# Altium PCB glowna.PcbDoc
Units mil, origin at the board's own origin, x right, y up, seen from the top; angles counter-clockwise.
Board outline 3802 x 3105 mil, 2 copper layers (Top Layer, Bottom Layer); 129 components, 124 nets, 433 pads, 98 vias.
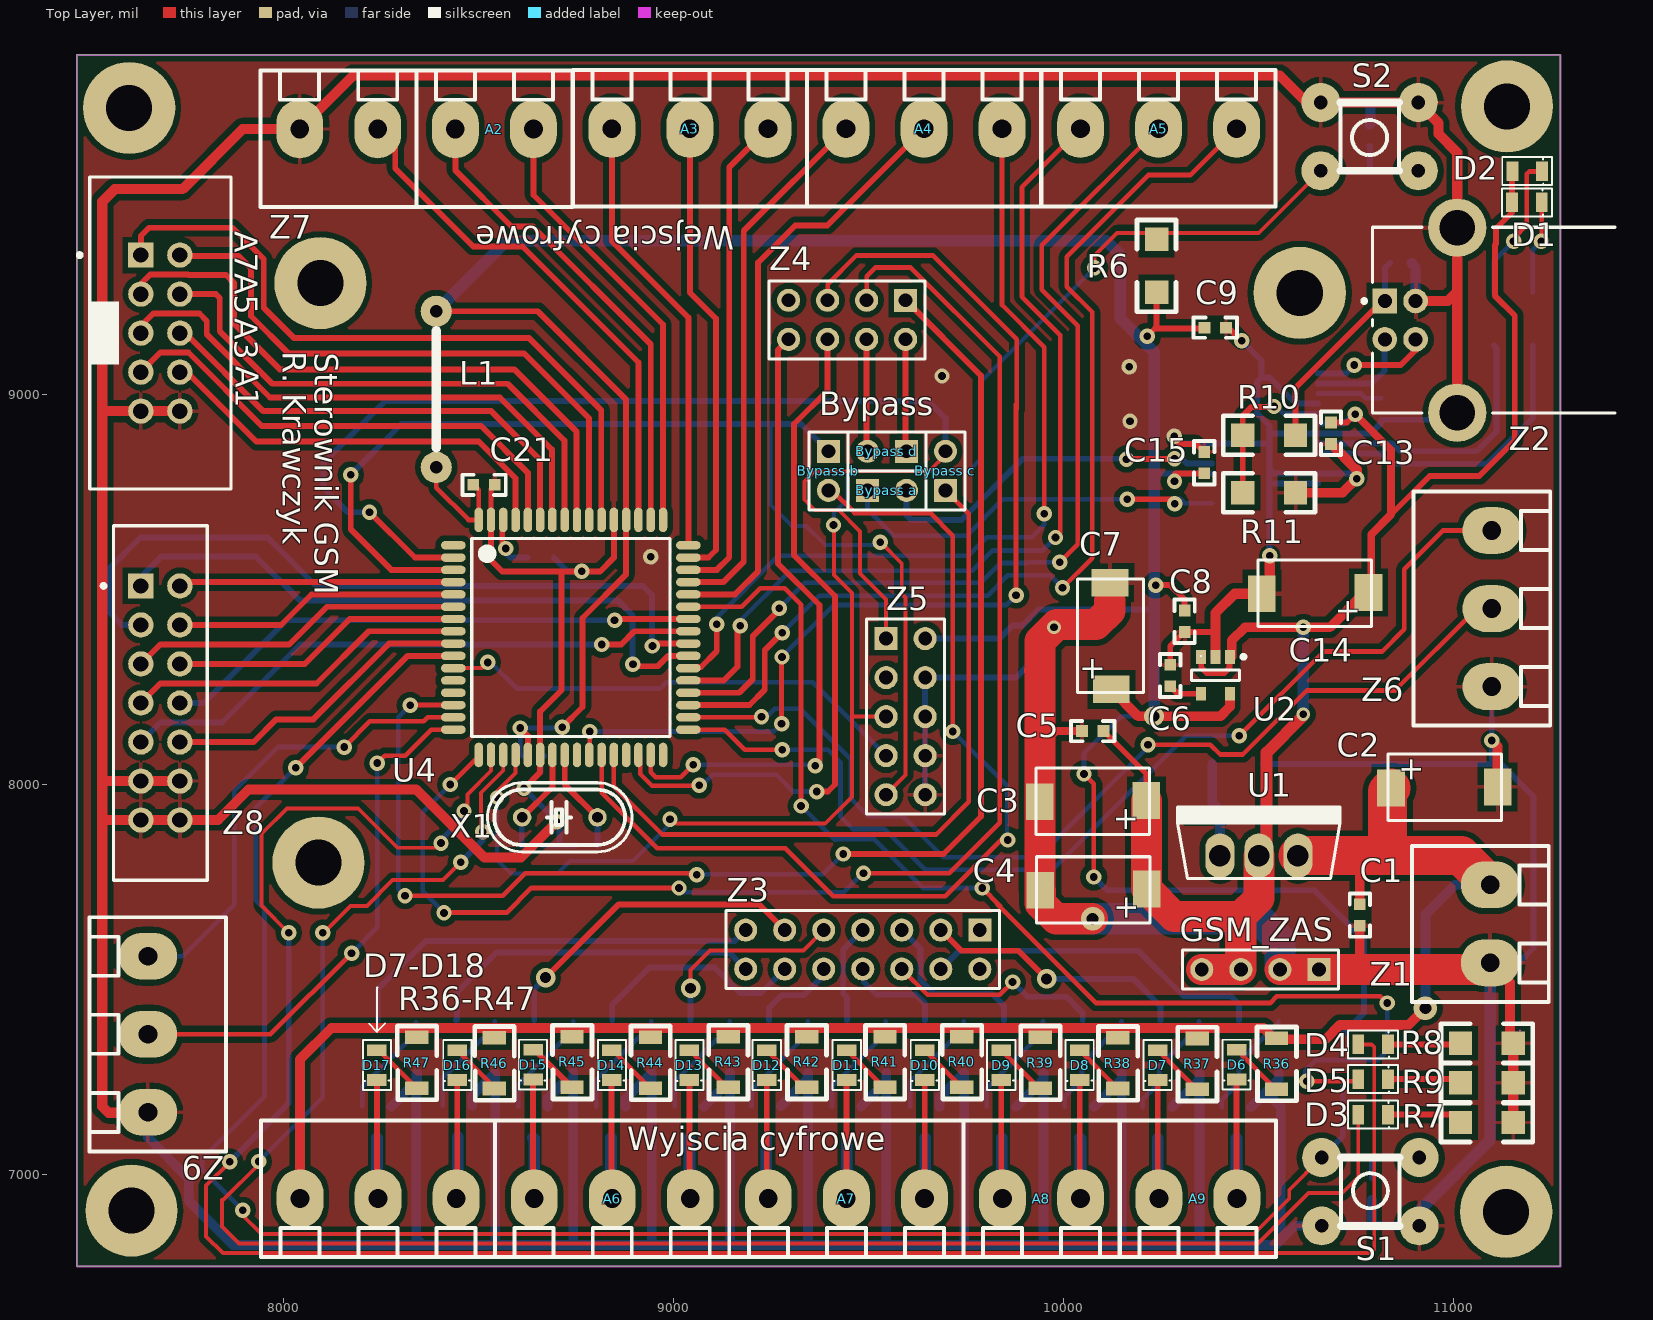
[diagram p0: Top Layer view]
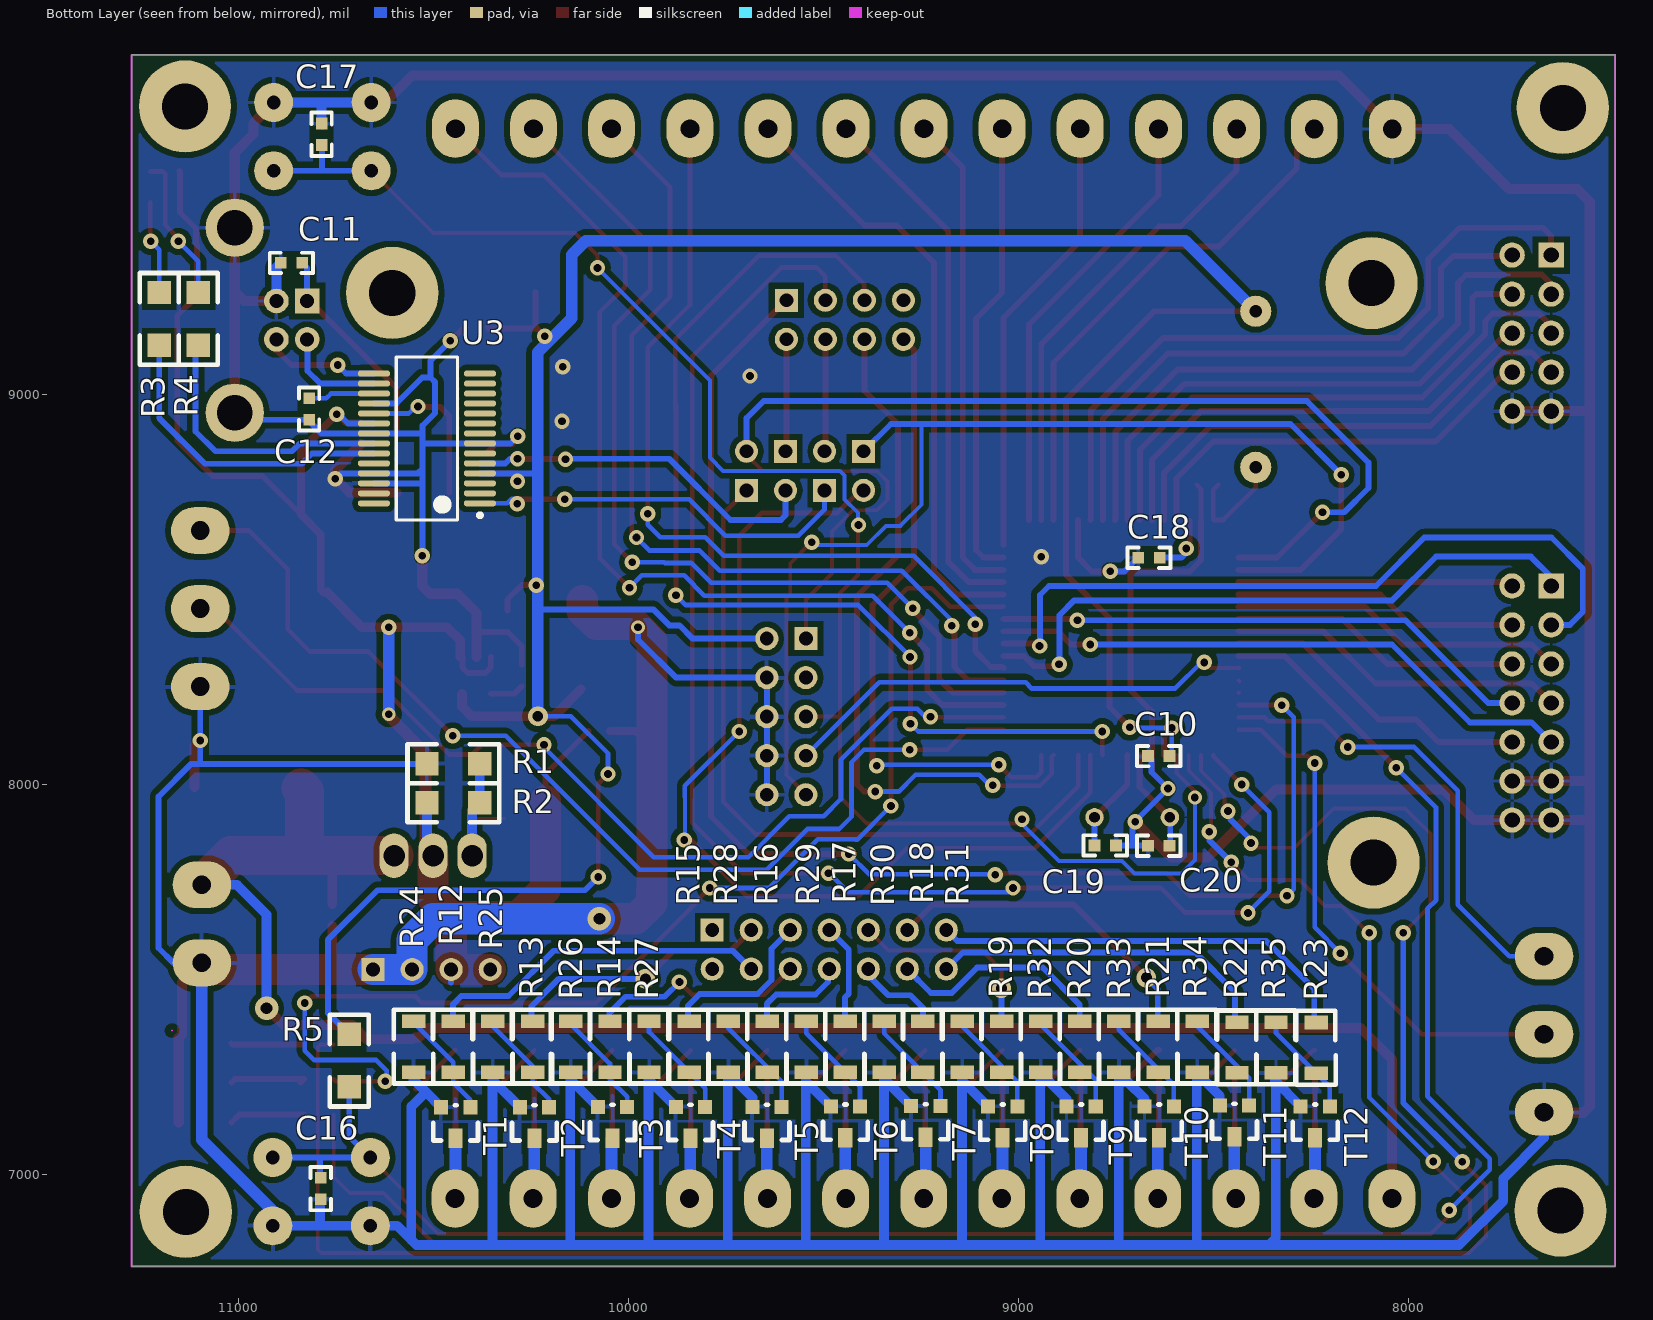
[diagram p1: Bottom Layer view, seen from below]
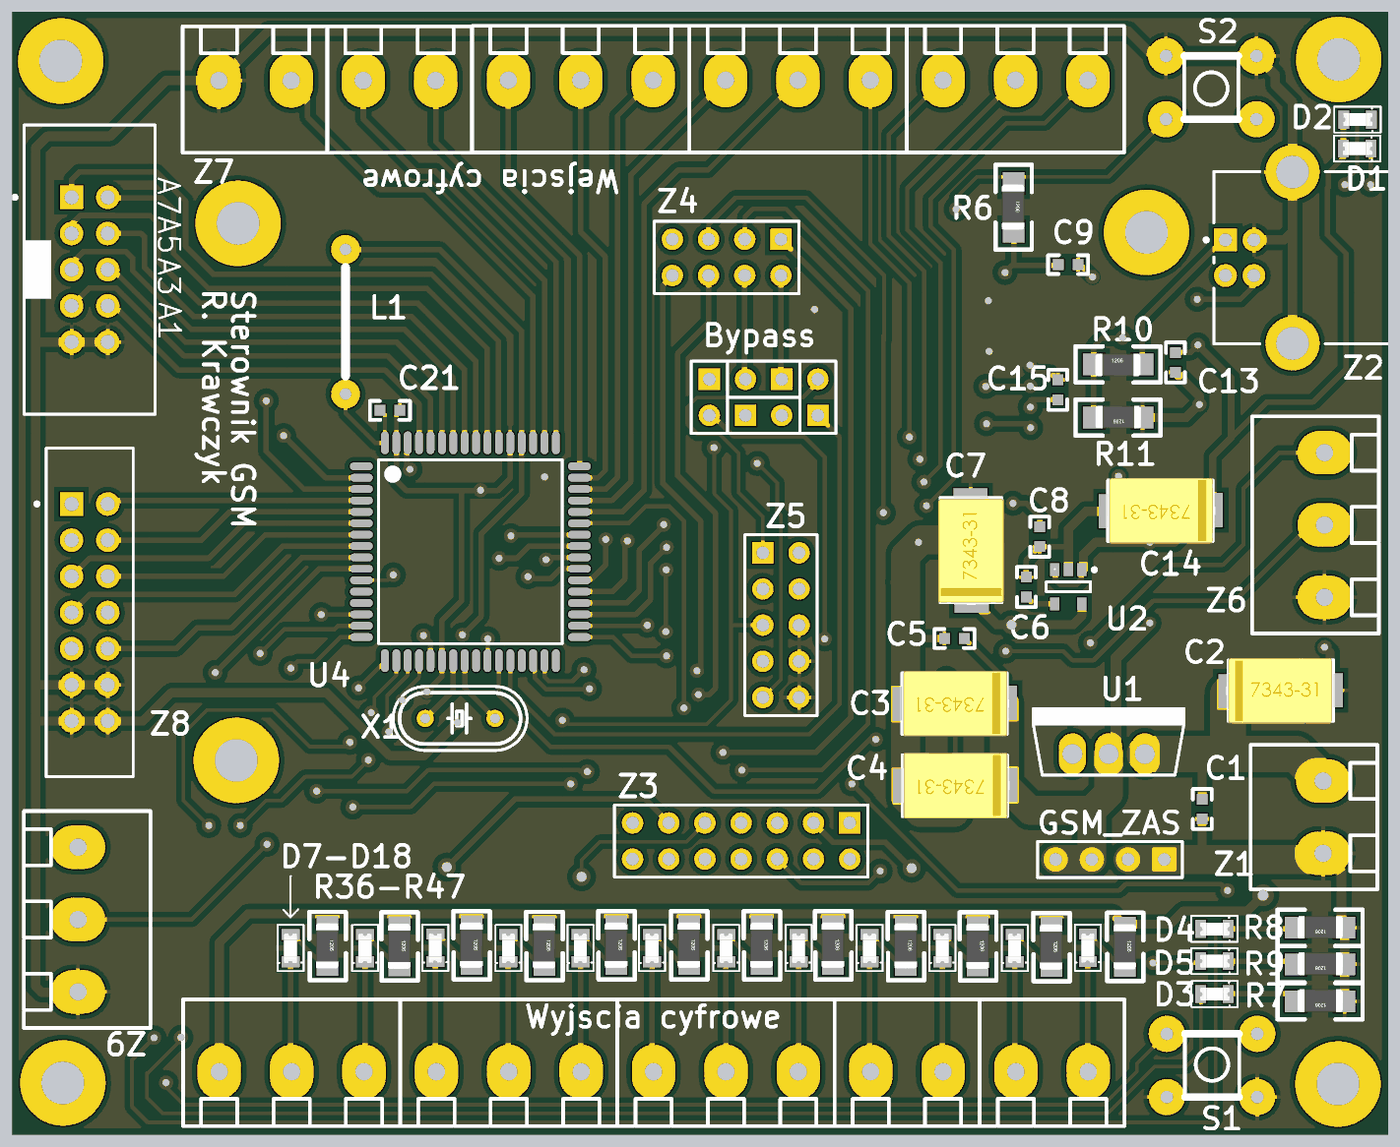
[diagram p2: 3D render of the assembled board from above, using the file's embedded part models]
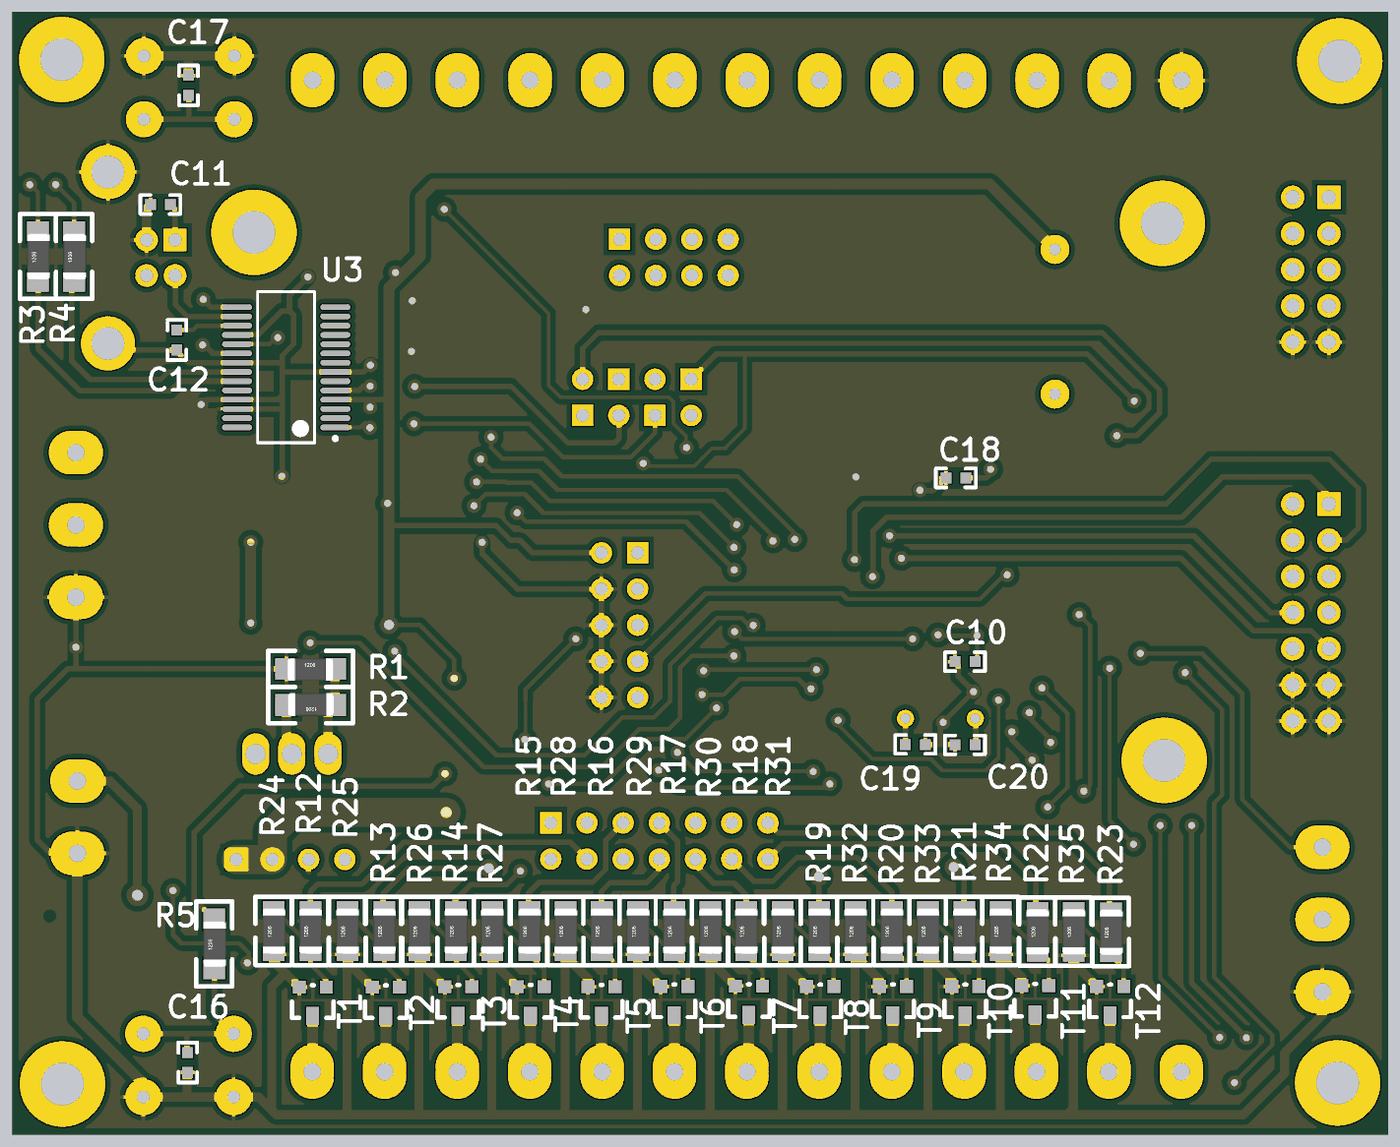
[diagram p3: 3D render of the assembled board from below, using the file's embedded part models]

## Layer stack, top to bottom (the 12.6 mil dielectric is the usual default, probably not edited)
Top Layer: signal copper 1.4
Dielectric: dielectric 12.6, FR-4, Dk 4.8
Bottom Layer: signal copper 1.4

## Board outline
11273,9870 7471,9870 7471,6765 11273,6765

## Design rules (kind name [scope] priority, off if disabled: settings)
Clearance [All] p1: gap=15
PlaneConnect PlaneConnect_1 [All] p1: planeconnectstyle=Relief reliefexpansion=20 reliefentries=4 reliefconductorwidth=10 reliefairgap=10
PolygonConnect [(InNet('GND') AND IsVia)] p1: connectstyle=Direct reliefconductorwidth=10 reliefentries=4 polygonreliefangle="90 Angle"
PolygonConnect PolygonConnect_1 [All] p2: connectstyle=Relief reliefconductorwidth=10 reliefentries=4 polygonreliefangle="90 Angle"
RoutingVias [All] p1: holewidth=19.68 width=39.37 viastyle="Through Hole" minholewidth=19.68 minwidth=31.5 maxholewidth=19.68 maxwidth=39.37
SilkscreenOverComponentPads [All] p1: minsilkscreentomaskgap=10
SolderMaskExpansion [All] p1: expansion=4
Width [All] p1: maxlimit=100 minlimit=10 preferedwidth=30 toplayer_prefwidth=10 minimp=50.000000 maximp=50.000000 favimp=50.000000
26 further rules are at their usual default settings.

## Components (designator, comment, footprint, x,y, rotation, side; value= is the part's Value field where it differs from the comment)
A2 "ARK2_1" ARK2 9131,9650 r0 top
A3 "ARK3" ARK3 8842,9681 r0 top
A4 "ARK3" ARK3 9442,9681 r0 top
A5 "ARK3" ARK3 10043,9681 r0 top
A6 "ARK3" ARK3 9043,6939 r180 top
A7 "ARK3" ARK3 9643,6939 r180 top
A8 "ARK2_1" ARK2 9353,6969 r180 top
A9 "ARK2_1" ARK2 9754,6969 r180 top locked
"Bypass a" "Header 2" HDR1X2 9497,8754 r0 top
"Bypass b" "Header 2" HDR1X2 9397,8854 r270 top
"Bypass c" "Header 2" HDR1X2 9697,8754 r90 top
"Bypass d" "Header 2" HDR1X2 9597,8854 r180 top
C1 "100nF" 0603 10759,7693 r270 top
C2 "CAP2" smd-d 10976,7993 r270 top
C3 "1500uF" smd-d 10075,7957 r90 top
C4 "1500uF" smd-d 10076,7730 r90 top
C5 "100nF" 0603 10102,8137 r180 top
C6 "100nF" 0603 10273,8307 r270 top
C7 "1500uF" smd-d 10120,8381 r0 top
C8 "3x100nF" 0603 10310,8446 r270 top
C9 "3x100nF" 0603 10361,9171 r0 top
C10 "3x100nF" 0603 8613,8073 r0 bottom
C11 "100nF" 0603 10836,9337 r0 bottom
C12 "100nF" 0603 10818,8990 r270 bottom
C13 "100nF" 0603 10685,8928 r270 top
C14 "100uF" smd-d 10644,8490 r90 top
C15 "100nF" 0603 10360,8797.43 r90 top
C16 "33pF" 0603 10788,6937 r90 bottom
C17 "33pF" 0603 10786,9694 r270 bottom
C18 "100nF" 0603 8638,8581 r0 bottom
C19 "33pF" 0603 8805,7844 r180 bottom
C20 "33pF" 0603 8613,7843 r0 bottom
C21 "100nF" 0603 8542,8768 r180 top
D1 "" led_0805 11174,9498 r270 top
D2 "" led_0805 11175,9578 r270 top
D3 "" led_0805 10780,7160 r270 top
D4 "" led_0805 10780,7340 r270 top
D5 "" led_0805 10780,7251 r270 top
D6 "" led_0805 10449,7295 r180 top
D7 "" led_0805 10247,7294 r180 top
D8 "" led_0805 10047,7294 r180 top
D9 "" led_0805 9846,7294 r180 top
D10 "" led_0805 9650,7294 r180 top
D11 "" led_0805 9450,7294 r180 top
D12 "" led_0805 9245,7294 r180 top
D13 "" led_0805 9047,7294 r180 top
D14 "" led_0805 8848,7294 r180 top
D15 "" led_0805 8646,7295 r180 top
D16 "" led_0805 8452,7294 r180 top
D17 "" led_0805 8246,7294 r180 top
GSM_ZAS "Header 4" HDR1X4 10654,7526 r180 top locked
L1 "10uH" r4 8392,8813 r0 top
R1 "RES" 1206#1 10516,8053 r180 bottom
R2 "RES" 1206#1 10381,7953 r0 bottom
R3 "470R" 1206#1 11202,9126 r90 bottom
R4 "470R" 1206#1 11102,9126 r90 bottom
R5 "10k" 1206#1 10715,7225 r90 bottom
R6 "10k" 1206#1 10238,9397 r270 top
R7 "1k" 1206#1 11152,7134 r180 top
R8 "1k" 1206#1 11152,7337 r180 top
R9 "1k" 1206#1 11152,7236 r180 top
R10 "4,7k" 1206#1 10459,8895 r0 top
R11 "10k" 1206#1 10594,8748 r180 top
R12 "2,2k" 1206#2 10450,7261 r90 bottom
R13 "2,2k" 1206#2 10246,7261 r90 bottom
R14 "2,2k" 1206#2 10048,7261 r90 bottom
R15 "2,2k" 1206#2 9845,7261 r90 bottom
R16 "2,2k" 1206#2 9645,7261 r90 bottom
R17 "2,2k" 1206#2 9445,7261 r90 bottom
R18 "2,2k" 1206#2 9246,7261 r90 bottom
R19 "2,2k" 1206#2 9044,7261 r90 bottom
R20 "2,2k" 1206#2 8844,7261 r90 bottom
R21 "2,2k" 1206#2 8643,7261 r90 bottom
R22 "2,2k" 1206#2 8441,7259 r90 bottom
R23 "2,2k" 1206#2 8238,7258 r90 bottom
R24 "47K" 1206#2 10551,7261 r90 bottom
R25 "47K" 1206#2 10348,7261 r90 bottom
R26 "47K" 1206#2 10149,7261 r90 bottom
R27 "47K" 1206#2 9948,7261 r90 bottom
R28 "47K" 1206#2 9745,7261 r90 bottom
R29 "47K" 1206#2 9545,7261 r90 bottom
R30 "47K" 1206#2 9345,7261 r90 bottom
R31 "47K" 1206#2 9145,7261 r90 bottom
R32 "47K" 1206#2 8944,7261 r90 bottom
R33 "47K" 1206#2 8744,7261 r90 bottom
R34 "47K" 1206#2 8543,7261 r90 bottom
R35 "47K" 1206#2 8341,7259 r90 bottom
R36 "2.2k" 1206#2 10546.5,7351.5 r270 top
R37 "2.2k" 1206#2 10343,7351 r270 top
R38 "2.2k" 1206#2 10140,7353 r270 top
R39 "2.2k" 1206#2 9941,7354 r270 top
R40 "2.2k" 1206#2 9740,7356 r270 top
R41 "2.2k" 1206#2 9543,7356 r270 top
R42 "2.2k" 1206#2 9342,7356 r270 top
R43 "2.2k" 1206#2 9141,7356 r270 top
R44 "2.2k" 1206#2 8942,7354 r270 top
R45 "2.2k" 1206#2 8741,7356 r270 top
R46 "2.2k" 1206#2 8542,7353 r270 top
R47 "2.2k" 1206#2 8343,7354 r270 top
S1 "MSWITCH" MSWITCH 10661,6869 r90 top
S2 "MSWITCH" MSWITCH 10909,9748 r270 top
T1 "BC548B" "sot-23 rk" 10405,7173 r0 bottom
T2 "BC548B" "sot-23 rk" 10203,7173 r0 bottom
T3 "BC548B" "sot-23 rk" 10003,7174 r0 bottom
T4 "BC548B" "sot-23 rk" 9803,7174 r0 bottom
T5 "BC548B" "sot-23 rk" 9607,7174 r0 bottom
T6 "BC548B" "sot-23 rk" 9406,7175 r0 bottom
T7 "BC548B" "sot-23 rk" 9200,7176 r0 bottom
T8 "BC548B" "sot-23 rk" 9003,7175 r0 bottom
T9 "BC548B" "sot-23 rk" 8802,7175 r0 bottom
T10 "BC548B" "sot-23 rk" 8602,7175 r0 bottom
T11 "BC548B" "sot-23 rk" 8409,7177 r0 bottom
T12 "BC548B" "sot-23 rk" 8202,7175 r0 bottom
U1 "LM350" to220v 10500,7822 r0 top
U2 "LP3985" sot23-5al 10389,8280 r270 top
U3 "FT232RL" SSOP-28 10516,8887 r0 bottom
U4 "ATMEGA128_TQFP64" atmega128 8737,8377 r0 top locked
"Wejscia cyfrowe" "ARK2_1" ARK2 8732,9650 r0 top
"Wyjscia cyfrowe" "ARK3" ARK3 8443,6939 r180 top
X1 "X" X 8805,7916 r180 top
Z1 "12V" ARK2 11063,7053 r270 top
Z2 "USB_con" usb2.5-2h4f 11414,9190 r0 top
Z3 "GSM_GPIO" HDR2X7_CEN 9785,7627 r180 top locked
Z4 "GSM" HDR2X4_CEN 9595,9241 r180 top locked
Z5 "AVR_PROG" hdr2x5 9545,8374 r270 top
Z6 "ARK3" ARK3 11097,8651 r270 top
Z7 "Analog IN" idc2.54-v10d 7685,9157 r270 top
Z8 "Header 7X2" idc2.54-v14c 7685,8209 r270 top
Z9 "Header 3" ark3 7653,7160 r90 top

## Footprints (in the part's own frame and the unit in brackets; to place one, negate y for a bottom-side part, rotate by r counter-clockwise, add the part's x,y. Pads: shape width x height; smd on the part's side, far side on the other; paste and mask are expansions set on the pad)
0603 [mil]
  rect 30x30 smd: 1(0,0) 2(55,0)
  silkscreen extent -28,-26 83,26
1206#1 [mil]
  rect 60x60 smd: 1(0,0) 2(135,0)
  silkscreen extent -50,-50 185,50, body extent 4,-33 130,30, height 39
1206#2 [mil]
  rect 35x60 smd: 1(2,-1) 2(132,-1)
  silkscreen extent -27,-51 162,50, body extent 4,-33 130,30, height 39
ARK2 [mil]
  oval 120x150 hole 48: 1(-690,30) 2(-490,30)
  silkscreen extent -790,-170 -390,180
ARK3 [mil]
  oval 120x150 hole 48: 1(0,0) 2(200,0) 3(400,0)
  silkscreen extent -100,-200 500,150
ark3 [mil]
  oval 120x150 hole 48: 1(0,0) 2(200,0) 3(400,0)
  silkscreen extent -100,-200 500,150
atmega128 [mm] "TQFP64-0.8"
  oval 1.6x0.55 smd: 1(-7.65,6) 2(-7.65,5.2) 3(-7.65,4.4) 4(-7.65,3.6) 5(-7.65,2.8) 6(-7.65,2) 7(-7.65,1.2) 8(-7.65,0.4) 9(-7.65,-0.4) 10(-7.65,-1.2) 11(-7.65,-2) 12(-7.65,-2.8) 13(-7.65,-3.6) 14(-7.65,-4.4) 15(-7.65,-5.2) 16(-7.65,-6) 33(7.65,-6) 34(7.65,-5.2) 35(7.65,-4.4) 36(7.65,-3.6) 37(7.65,-2.8) 38(7.65,-2) 39(7.65,-1.2) 40(7.65,-0.4) 41(7.65,0.4) 42(7.65,1.2) 43(7.65,2) 44(7.65,2.8) 45(7.65,3.6) 46(7.65,4.4) 47(7.65,5.2) 48(7.65,6)
  oval 0.55x1.6 smd: 17(-6,-7.65) 18(-5.2,-7.65) 19(-4.4,-7.65) 20(-3.6,-7.65) 21(-2.8,-7.65) 22(-2,-7.65) 23(-1.2,-7.65) 24(-0.4,-7.65) 25(0.4,-7.65) 26(1.2,-7.65) 27(2,-7.65) 28(2.8,-7.65) 29(3.6,-7.65) 30(4.4,-7.65) 31(5.2,-7.65) 32(6,-7.65) 49(6,7.65) 50(5.2,7.65) 51(4.4,7.65) 52(3.6,7.65) 53(2.8,7.65) 54(2,7.65) 55(1.2,7.65) 56(0.4,7.65) 57(-0.4,7.65) 58(-1.2,7.65) 59(-2,7.65) 60(-2.8,7.65) 61(-3.6,7.65) 62(-4.4,7.65) 63(-5.2,7.65) 64(-6,7.65)
  silkscreen extent -6.45,-6.45 6.45,6.45, body extent -7,-7 7,7, height 1.2
HDR1X2 [mm] "Connector; Header; 2 Position"
  rect 1.5x1.5 hole 0.9: 1(0,0)
  round 1.5 hole 0.9: 2(2.54,0)
  silkscreen extent -1.27,-1.27 3.81,1.27
HDR1X4 [mm] "Connector; Header; 4 Position"
  rect 1.5x1.5 hole 0.9: 1(0,0)
  round 1.5 hole 0.9: 2(2.54,0) 3(5.08,0) 4(7.62,0)
  silkscreen extent -1.27,-1.27 8.89,1.27
HDR2X4_CEN [mm] "Connector; Header; 4x2 Position"
  rect 1.5x1.5 hole 0.9: 1(0,0)
  round 1.5 hole 0.9: 2(2.54,0) 3(5.08,0) 4(7.62,0) 5(0,2.54) 6(2.54,2.54) 7(5.08,2.54) 8(7.62,2.54)
  silkscreen extent -1.27,-1.27 8.89,3.81
hdr2x5 [mm] "Connector; Header; 5x2 Position"
  rect 1.5x1.5 hole 0.9: 1(0,0)
  round 1.5 hole 0.9: 2(0,2.54) 3(2.54,0) 4(2.54,2.54) 5(5.08,0) 6(5.08,2.54) 7(7.62,0) 8(7.62,2.54) 9(10.16,0) 10(10.16,2.54)
  silkscreen extent -1.27,-1.27 11.43,3.81
HDR2X7_CEN [mm] "Connector; Header; 7x2 Position"
  rect 1.5x1.5 hole 0.9: 1(0,0)
  round 1.5 hole 0.9: 2(2.54,0) 3(5.08,0) 4(7.62,0) 5(10.16,0) 6(12.7,0) 7(15.24,0) 8(0,2.54) 9(2.54,2.54) 10(5.08,2.54) 11(7.62,2.54) 12(10.16,2.54) 13(12.7,2.54) 14(15.24,2.54)
  silkscreen extent -1.27,-1.27 16.51,3.81
idc2.54-v10d [mm] "Connector; IDC, Low Profile Male Header, Thru-Hole; 10 Position; Vertical; Pitch 2.54 mm; Body 20.32 x 9.2 x 9.45 mm (LxWxH)"
  rect 1.65x1.65 hole 1: 1(-5.08,-1.27)
  round 1.65 hole 1: 2(-5.08,1.27) 3(-2.54,-1.27) 4(-2.54,1.27) 5(0,-1.27) 6(0,1.27) 7(2.54,-1.27) 8(2.54,1.27) 9(5.08,-1.27) 10(5.08,1.27)
  silkscreen extent -10.16,-5.37 10.16,4.6, body extent -10.16,-4.6 10.16,4.6, height 9.45
idc2.54-v14c [mm] "Connector; IDC, PCB Transition - 2 Rows, Thru-Hole; 14 Position; Vertical; Pitch 2.54 mm; Body 23.08 x 6.1 x 7.45 mm (LxWxH), Kinked Contacts"
  rect 1.65x1.65 hole 1: 1(-7.62,-1.27)
  round 1.65 hole 1: 2(-7.62,1.27) 3(-5.08,-1.27) 4(-5.08,1.27) 5(-2.54,-1.27) 6(-2.54,1.27) 7(0,-1.27) 8(0,1.27) 9(2.54,-1.27) 10(2.54,1.27) 11(5.08,-1.27) 12(5.08,1.27) 13(7.62,-1.27) 14(7.62,1.27)
  silkscreen extent -11.54,-3.82 11.54,3.05, body extent -11.54,-3.05 11.54,3.05, height 7.45
led_0805 [mil]
  rect 50x30 smd: 1(6,-25) 2(6,51)
  silkscreen extent -30,-51 42,77, body extent -12,-27 24,55, height 33
MSWITCH [mil]
  round 100 hole 35: 1(0,0) 1(0,-250) 2(175,0) 2(175,-250)
  silkscreen extent 0,-200 175,-50
r4 [mil]
  round 80 hole 32: 1(0,0) 2(0,400)
  silkscreen extent 0,50 0,350
smd-d [mil]
  rect 94.49x70.87 smd: 1(2,-137) 2(-1,136)
  silkscreen extent -85,-145 85,146, body extent -90,-151 91,148, height 122
sot23-5al [mm] "SOT23, 5-Leads, Body 2.9x1.6mm, Pitch 0.95mm, Lead Span 2.8mm, IPC High Density"
  rect 0.9x0.65 smd: 1(-1.2,0.95) 2(-1.2,0) 3(-1.2,-0.95) 4(1.2,-0.95) 5(1.2,0.95)
  silkscreen extent -1.32,-1.55 0.35,1.95, body extent -0.9,-1.55 0.9,1.55, height 1.45
"sot-23 rk" [mil]
  rect 35.98x35.98 smd: 1(75,0) 2(0,0)
  rect 35.98x50 smd: 3(37.99,80)
  silkscreen extent -20,-5 95,85
SSOP-28 [mm] "28-Pin SSOP 0.65 mm Pitch"
  oval 2.1x0.4 smd: 1(-3.45,4.225) 2(-3.45,3.575) 3(-3.45,2.925) 4(-3.45,2.275) 5(-3.45,1.625) 6(-3.45,0.975) 7(-3.45,0.325) 8(-3.45,-0.325) 9(-3.45,-0.975) 10(-3.45,-1.625) 11(-3.45,-2.275) 12(-3.45,-2.925) 13(-3.45,-3.575) 14(-3.45,-4.225) 15(3.45,-4.225) 16(3.45,-3.575) 17(3.45,-2.925) 18(3.45,-2.275) 19(3.45,-1.625) 20(3.45,-0.975) 21(3.45,-0.325) 22(3.45,0.325) 23(3.45,0.975) 24(3.45,1.625) 25(3.45,2.275) 26(3.45,2.925) 27(3.45,3.575) 28(3.45,4.225)
  silkscreen extent -3.57,-5.3 2,5.3, body extent -2.7,-5.3 2.7,5.3, height 2
to220v [mil]
  oval 75x114.37 hole 55: 1(-99.68,-4.25) 2(0.32,-4.25) 3(100.32,-4.25)
  Top Layer region: -185.04,86.61 -90.55,86.61 -90.55,94.49 -185.04,94.49
  silkscreen extent -208,-63 209,122
usb2.5-2h4f [mm] "Connector; USB1.1, Type B, Thru-Hole; 4 Position; Right Angle"
  rect 1.6x1.6 hole 0.92: 1(-15.01,1.25)
  round 1.6 hole 0.92: 2(-15.01,-1.25) 3(-13.01,-1.25) 4(-13.01,1.25)
  round 3.8 hole 2.3: 5(-10.3,6.02) 6(-10.3,-6.02)
  silkscreen extent -16.48,-6.05 -0.02,6.05, body extent -15.82,-6.05 -0.02,6.05, height 10.95
X [mm]
  round 1.2 hole 0.7: 1(0,0) 2(4.9,0)
  silkscreen extent -2.25,-2.25 7.15,2.25

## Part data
"Bypass a" "Bypass b" "Bypass c" "Bypass d": "Header, 2-Pin"
C1 C5 C6 C8 C9 C10 C11 C12 C13 C15 C16 C17 C18 C19 C20 C21: library part CAP, "Condenstor"
C2: "kONDENSATOR ELEKTROLITYCZNY"
C3 C4 C7 C14: library part CAP2, "kONDENSATOR ELEKTROLITYCZNY"
D1 D2 D3 D4 D5 D6 D7 D8 D9 D10 D11 D12 D13 D14 D15 D16 D17: library part LED0, "dioda elektroluminescencyjna LED"
GSM_ZAS: "Header, 4-Pin"
L1: library part cewka
R1 R2: "Rezystor"
R3 R4 R5 R6 R7 R8 R9 R10 R11 R12 R13 R14 R15 R16 R17 R18 R19 R20 R21 R22 R23 R24 R25 R26 R27 R28 R29 R30 R31 R32 R33 R34 R35 R36 R37 R38 R39 R40 R41 R42 R43 R44 R45 R46 R47: library part RES, "Rezystor"
T1 T2 T3 T4 T5 T6 T7 T8 T9 T10 T11 T12: "Tranzystor NPN"
U1: library part LM317, "3-Terminal Adjustable Positive Voltage Regulator"
U2: library part LM3985, "Stabilizator 2.8V"
U3: library part IC_FT232RL, "FT232R USB UART"
U4: "Atmel AVR 8bit - Mega Family"
X1: "Kwarc"
Z1: library part ARK
Z3: library part "Header 7X2A", "Header, 7-Pin, Dual row"
Z4: library part "Header 4X2A", "Header, 4-Pin, Dual row"
Z7: library part "Header 5X2", "Header, 5-Pin, Dual row"
Z8: "Header, 7-Pin, Dual row"
Z9: "Header, 3-Pin"

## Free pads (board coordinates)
  round 236.22 hole 118.11: 0(10605,9260) 1(8090,7800) 2(8095,9285) 3(7611,6908) 4(7605,9734) 5(11136,9738) 6(11134,6905)

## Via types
v1: diameter 39.37, hole 19.68, Top Layer to Bottom Layer, tented both sides, 89 vias
v2: diameter 35.43, hole 19.68, Top Layer to Bottom Layer, tented both sides, 3 vias
v3: diameter 50, hole 28, Top Layer to Bottom Layer, tented both sides, 3 vias
v4: diameter 60, hole 30, Top Layer to Bottom Layer, tented both sides, 2 vias
v5: diameter 51.18, hole 27.56, Top Layer to Bottom Layer, tented both sides, 1 vias

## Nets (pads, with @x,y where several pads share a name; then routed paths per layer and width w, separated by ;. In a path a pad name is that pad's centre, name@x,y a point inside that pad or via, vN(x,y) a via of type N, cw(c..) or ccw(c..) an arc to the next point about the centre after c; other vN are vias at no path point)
+2.8V: C7.1 C8.1 C9.1 C10.1 C15.1 L1.2 R5.2 R6.2 U2.5 U3.4 U4.21 U4.52 Z5.2 | length 7953.5
  Top Layer w12: v1(10052,8027) 10077,8002 v1(10077,7763)
  Top Layer w15: L1.2@8417,9213 8652,9213 8878.73,8986.27 U4.52 8878.73,8538.73 8767,8427 8767,8199 v1(8715,8147) ; v1(8607,8145) 8626.76,8125.24 U4.21 ; v1(10214,9149) 10234,9169 10238,9169 ; v1(10236,8511) 10273,8511 10310,8474 C8.1 ; R6.2 10238,9169 ; v1@10285,8785 10285,8796 10286.43,8797.43 C15.1 ; C9.1 10359,9169 10238,9169
  Top Layer w25: C7.1 10191,8175 v5(10232,8175) 10401.8,8175 10426.4,8199.6 U2.5
  Bottom Layer w12: C10.1 8607,8079 v1(8607,8145) 8713,8145 v1(8715,8147) ; v1(10052,8027) 10052,8080 10147,8175 v5(10232,8175)
  Bottom Layer w15: Z5.2 9835,8374 9869,8408 9895,8408 9936,8449 10229,8449 10232,8452 ; v1(10077,7763) 10111,7729 10643,7729 10770,7602 10770,7415 R5.2 ; 10232,8797 10232.43,8797.43 U3.4
  Bottom Layer w30: L1.2 8573,9394 10109,9394 10145,9358 10145,9195 10232,9108 10232,8797 10232,8452 v5(10232,8175)
  other v1: 10284,8777
+12V: "Wyjscia cyfrowe.3" C1.1 C2.1 R36.1 R37.1 R38.1 R39.1 R40.1 R41.1 R42.1 R43.1 R44.1 R45.1 R46.1 R47.1 U1.3 Z1.1 | length 4582.6
  Top Layer w25: 8043,6939 8043,7296 8123,7376 9342,7376 9941,7376 10512,7376 10536.5,7351.5 10546.5,7351.5 10551,7347 10671,7347 10707.5,7383.5 10883.5,7383.5 v4(10927,7427) ; 10758,7817.75 10759,7816.75 C1.1
  Top Layer w100: U1.3 10758,7817.75 10830,7817.75 ; C2.1 10830,7982 10830,7817.75 ; Z1.1 11018.25,7817.75 10830,7817.75
  Bottom Layer w25: v4(10927,7427) 10927,7667 11003,7743 Z1.1
ADC0: U4.61 Z7.8 | length 1079.6
  Top Layer w15: Z7.8 7753,9057 7931,8879 8501,8879 8595,8785 8595,8761 8595.27,8760.73 U4.61
ADC1: U4.60 Z7.7 | length 1261
  Top Layer w15: Z7.7 7685.02,9106.98 7757.02,9106.98 7945,8919 8507,8919 8626.76,8799.24 U4.60
ADC2: U4.59 Z7.6 | length 1226.5
  Top Layer w15: Z7.6 7749,9157 7949,8957 8105,8957 ; 8120,8957 8105,8957 ; U4.59 8658.26,8831.74 8533,8957 8105,8957
ADC3: U4.58 Z7.5 | length 1429.9
  Top Layer w15: Z7.5 7635,9175 7667,9207 7785,9207 7804,9188 7804,9154 7966,8992 8555,8992 8688.76,8858.24 8688.76,8679.18 U4.58
ADC4: U4.57 Z7.4 | length 1394.5
  Top Layer w15: Z7.4 7827,9257 7837,9247 7837,9162 7972,9027 8575,9027 8720.25,8881.75 8720.25,8679.18 U4.57
ADC5: U4.56 Z7.3 | length 1615.7
  Top Layer w15: Z7.3 7635,9283 7658.98,9306.98 7755.7,9306.98 7756.68,9306 7853,9306 7874,9285 7874,9181 7991,9064 8592,9064 8751.75,8904.25 8751.75,8778 ; 8751.75,8769.18 8751.75,8778 ; U4.56 8751.75,8679.18 8751.75,8778
ADC6: U4.55 Z7.2 | length 1553.9
  Top Layer w15: Z7.2 7737,9355 7885,9355 7917,9323 7917,9201 8013,9105 8617,9105 8783.24,8938.76 8783.24,8679.18 U4.55
ADC7: U4.54 Z7.1 | length 1785.9
  Top Layer w15: Z7.1 7635,9406 7656,9427 7870,9427 7950,9347 7950,9222 8028,9144 8630,9144 8814.74,8959.26 8814.74,8679.18 U4.54
ALERT1: U4.33 Z6.1 | length 2739
  Top Layer w12: U4.33 9131.22,8140.78 9183,8089 v1(9279,8089) ; v1(10450,8125) 10666,8341 10816,8341 10873,8398 10873,8552 10972,8651 Z6.1
  Bottom Layer w12: v1(9279,8089) 9396,8089 9428,8057 9428,7918 9460,7886 9541,7886 9645,7782 9971,7782 10314,8125 v1(10450,8125)
ALERT2: U4.34 Z6.2 | length 2573.1
  Top Layer w12: U4.34 v1@9224.22,8172.28 ; v1(10216,8102) 10376,8102 10401,8077 10459,8077 10623,8241 10849,8241 11059,8451 Z6.2
  Bottom Layer w12: v1@9227.68,8173.69 v1(9225.63,8173.69) 9238.68,8173.69 9259,8194 9324.94,8194 9455,8063.94 9455,7963 9499,7919 9587,7919 9692,7814 9935,7814 10216,8095 v1(10216,8102)
DIG1: A5.3 U4.35 | length 2647.1
  Top Layer w12: v1(9997,8504) 10073,8580 10073,9211 10008,9276 10008,9353 10217,9562 10324,9562 A5.3
  Top Layer w15: U4.35 9194.77,8203.77 9234,8243 9234,8344 v1(9279,8389)
  Bottom Layer w12: v1(9279,8389) 9374,8484 9805,8484 9857,8536 9965,8536 v1(9997,8504)
DIG2: A5.2 U4.36 | length 2449.3
  Top Layer w12: v1(9990,8570) 10036,8616 10036,9176 9944,9268 9944,9382 A5.2
  Top Layer w15: U4.36 9168.27,8235.27 9203,8270 9203,8380 9271,8448 v1(9271,8452)
  Bottom Layer w12: v1(9271,8452) 9336,8517 9788,8517 9839,8568 9906,8568 9908,8570 v1(9990,8570)
DIG3: A5.1 U4.37 | length 2313.2
  Top Layer w12: v1(9979,8633) 9991,8645 9991,9152 9893,9250 9893,9531 A5.1
  Top Layer w15: U4.37 9128.76,8266.76 9164,8302 v1@9164,8413
  Bottom Layer w12: v1@9164,8413 9299,8548 9766,8548 9818,8600 9946,8600 v1(9979,8633)
  other v1: 9171,8407
DIG4: A4.3 U4.38 | length 2183.3
  Top Layer w12: A4.3 9842,9229 9950,9121 v1(9950,8694)
  Top Layer w15: U4.38 9041.35,8301.43 9070.58,8301.43 9111,8341.85 v1(9111,8411)
  Bottom Layer w12: v1(9111,8411) 9111,8428 9269,8586 9755,8586 9803,8634 9894,8634 ; 9903,8634 9894,8634 ; v1(9950,8694) 9950,8666 9918,8634 9894,8634
DIG5: A4.2 U4.44 | length 1561.6
  Top Layer w15: U4.44 9157.24,8487.24 9217,8547 9217,9338 9312,9433 9394,9433 A4.2
DIG6: A4.1 U4.45 | length 1382
  Top Layer w15: U4.45 9127.73,8518.73 9180,8571 9180,9419 A4.1
DIG7: A3.3 U4.46 | length 1258
  Top Layer w15: U4.46 9111.23,8550.23 9143,8582 9143,9582 A3.3
DIG8: A3.2 U4.47 | length 1186.6
  Top Layer w15: U4.47 9089.72,8581.72 9109,8601 9109,9194 9042,9261 A3.2
DIG9: A3.1 U4.48 | length 1149
  Top Layer w15: A3.1 8842,9393 9038.18,9196.82 U4.48
DIG10: A2.2 U4.49 | length 1139.4
  Top Layer w15: A2.2 8641,9511 8973.22,9178.78 U4.49
DIG11: A2.1 U4.50 | length 1241.4
  Top Layer w15: A2.1 8441,9574 8585,9430 8640,9430 8941.72,9128.28 U4.50
DIG12: "Wejscia cyfrowe.2" U4.51 | length 1352.4
  Top Layer w15: 8242,9680 8287,9635 8287,9579 8487,9379 8613,9379 8910.23,9081.77 U4.51
DTR: U4.14 Z4.1 | length 3584.5
  Top Layer w12: v1(8312,7715) 8562,7715 8620,7773 9038,7773 9042,7769 v1(9060,7769) ; v1(8325,8203) 8325.77,8203.77 U4.14
  Top Layer w15: v1(9435,7822) 9692,7822 9788,7918 9788,9048 Z4.1
  Bottom Layer w12: v1(8312,7715) 8295,7732 8295,8173 v1(8325,8203) ; v1@9060,7770 9383,7770 v1(9435,7822)
GND: "Wejscia cyfrowe.1" C1.2 C2.2 C3.2 C4.2 C5.2 C6.1 C7.2 C8.2 C9.2 C10.2 C11.2 C12.2 C13.2 C14.2 C15.2 C16.1 C17.1 C18.2 C19.2 C20.2 C21.1 GSM_ZAS.1 GSM_ZAS.2 R1.1 R7.1 R8.1 R9.1 R11.1 R24.1 R25.1 R26.1 R27.1 R28.1 R29.1 R30.1 R31.1 R32.1 R33.1 R34.1 R35.1 S1.1 S2.1 T1.1 T2.1 T3.1 T4.1 T5.1 T6.1 T7.1 T8.1 T9.1 T10.1 T11.1 T12.1 U2.2 U3.7 U3.18 U3.21 U3.25 U3.26 U4.22 U4.53 U4.63 Z1.2 Z2.4 Z2.5 Z5.4 Z5.6 Z5.8 Z5.10 Z6.3 Z7.9 Z7.10 Z8.11 Z8.12 Z8.13 Z8.14 Z9.1 | length 29683.9
  Top Layer w12: U4.63 8532.28,8757.28 C21.1@8543,8768
  Top Layer w15: U4.63 8532.28,8574.72 8561,8546 8812,8546 8847.24,8581.24 U4.53 ; v1(8617,7990) 8658.26,8031.26 U4.22 8658.26,8187.26 8713,8242 8713,8544 ; C6.1 10273,8355 10309,8391 10389,8391 ; v1@10285,8885 10297,8873 10339.43,8873 C15.2 ; C9.2 10422,9171 v1(10456,9137)
  Top Layer w20: 9939,8095 9981,8137 C5.2
  Top Layer w25: 7536,7904 7541,7909 Z8.13 Z8.14 7833,7909 7911,7987 8339,7987 8340,7988 8515,7813 8609,7813 v1(8701,7905) ; 7536,8007 7538,8009 Z8.11 Z8.12 ; R11.1 10715,8748 v1(10751,8784) ; 10753,7526 10759,7532 C1.2 ; v1(11097,8113) 11112,8098 C2.2
  Top Layer w26: Z9.1 7652,7159 7552,7159 7536,7175 7536,7904 7536,8007 7536,8958 ; Z7.10 Z7.9 7537,8957 7536,8958 ; U2.2 10389,8391 10389,8440 10438,8489 C14.2 10528,8509 v1(10528,8586) ; C13.2 10751,8807 v1(10751,8784) ; Z2.4 10984.21,9239.21 11008.49,9263.49 ; 11008.49,8952.99 11008.49,9263.49 ; Z1.2 11143.5,7492.5 11143.5,7359.44 11152,7350.94 R8.1 R9.1 R7.1 ; 7536,8958 7536,9494 7568,9526 7742,9526 7896,9680 8042,9680 8179,9817 10554,9817 10623,9748 10659,9748 10909,9748 10909,9747 10961,9695 10961,9667 11008.49,9619.51 Z2.5 11008.49,9263.49
  Top Layer w80: 9938,8292 9939,8291 ; v4(10074,7656) 9980,7656 9940,7696 C4.2 9939,7730 C3.2 9939,8095 9939,8291 ; 10118,8472 10118,8445 10083,8410 9982,8410 v2(9975,8403) 9939,8367 9939,8291 ; GSM_ZAS.2 GSM_ZAS.1 10753,7526 11076,7526 Z1.2
  Bottom Layer w15: C20.2@8666,7844 8708,7844 ; C10.2 8659,8064 8659,8032 v1(8617,7990) 8701.5,7905.5 v1(8701,7905) ; C18.2@8693,8582 8729,8546 8764,8546 v1(8765,8547) ; v1@8708,7899 8708,7844 ; C19.2 8708,7844 ; Z5.10 Z5.8 Z5.6 Z5.4 9877,8274 9975,8372 v2(9975,8403) ; v1@10283,8883 v1@10285,8885 ; v1(10283,8893) 10301.8,8874.2 U3.7 10526.2,8874.2 10527,8875 ; v1(10456,9137) 10507,9086 10507,9043 ; R1.1 11120,8053 11204,7969 11204,7581 11166,7543 Z1.2 ; v1(10528,8586) 10527,8587 10527,8776 ; U3.26 10531.16,8771.84 10527,8776 ; U3.18 10594.43,8976.57 10528,9043 10507,9043 ; v1@10737.57,8797.43 U3.25 10539.57,8797.43 10527,8810 ; 11008.49,8952.99 10990.5,8935 10814,8935 10814,8927 10786.8,8899.8 U3.21 10528.8,8899.8 10527,8898 ; Z6.3@11094,8252 11097,8249 v1@11097,8122 ; 11097,8057 v1(11097,8113) v1@11097,8122 ; 11097,8187 v1@11097,8122 ; 10507,9043 10495,9031 10495,8952 10527,8920 10527,8898 ; 10527,8776 10527,8810 ; 10527,8810 10527,8875 ; 10527,8875 10527,8898
  Bottom Layer w25: Z9.1 7653,7095 7757.61,6990.39 7757.61,6933.39 ; 7757.61,6933 7757.61,6933.39 ; T12.1 8343,7241 8343,7261 8341,7259 8341,6837 8358,6820 ; T11.1 8484,7202 8543,7261 8543,6827 8550,6820 ; T10.1 8677,7195 8719,7237 8743,7237 ; R33.1 8743,7237 ; T9.1 8877,7194 8944,7261 8944,6825 8949,6820 ; T8.1 9145,7242 ; R31.1@9145,7261 9145,7242 ; T7.1 R30.1@9345,7246 ; R30.1@9345,7261 R30.1@9345,7246 ; T6.1 9545,7239 ; R29.1@9545,7261 9545,7239 ; T5.1 9682,7198 9745,7261 9745,6824 9749,6820 ; T4.1 9948,7244 ; R27.1@9948,7261 9948,7244 ; T3.1 10149,7245 ; R26.1@10149,7261 10149,7245 ; T2.1 10348,7243 ; R25.1@10348,7261 10348,7243 ; T1.1 10519,7212 ; R1.1@10515,8054 R1.1 ; R24.1@10551,7261 10551,7244 10519,7212 ; C16.1@10790,6936 10790,6869 ; S1.1@10911,6869 10790,6869 ; 7757.61,6933.39 7871,6820 8358,6820 ; 8358,6820 8550,6820 ; 8550,6820 8747,6820 ; 8743,7237 8743,6824 8747,6820 ; 8747,6820 8949,6820 ; 8949,6820 9146,6820 ; 9145,7242 9145,6821 9146,6820 ; 9146,6820 9350,6820 ; R30.1@9345,7246 9345,6825 9350,6820 ; 9350,6820 9543,6820 ; 9543,6820 9749,6820 ; 9543,6820 9545,6822 9545,7239 ; 9749,6820 9954,6820 ; 9948,7244 9948,6826 9954,6820 ; 9954,6820 10151,6820 ; 10149,7245 10149,6822 10151,6820 ; 10151,6820 10350,6820 ; 10348,7243 10348,6822 10350,6820 ; 10350,6820 10543,6820 10556,6833 ; 10519,7212 10556,7175 10556,6833 ; 10556,6833 10592,6869 10661,6869 10790,6869
  Bottom Layer w26: S2.1@10659,9748 10786,9748 ; C17.1@10784,9692 C17.1 10786,9748 ; C11.2 10901.8,9326.2 Z2.4 ; S2.1@10909,9748 10786,9748
  Bottom Layer w30: S1.1@10911,6869 10911,6908 11093,7090 Z1.2
  Bottom Layer w80: v4(10074,7656) 10500,7656 10554,7602 GSM_ZAS.2 GSM_ZAS.1
  other v1: 8942,8584 10170,8931 9688,9047 10168,9071
GSM_RST: U4.30 Z4.7 | length 1819.3
  Top Layer w12: U4.30 8914.9,8071.15 8914.9,8026.99 8944.89,7997 9065,7997 v1(9066,7998)
  Top Layer w15: v1(9367,7982) 9396,7982 9414,8000 9414,8483 9309,8588 9309,8924 9395,9010 Z4.7
  Bottom Layer w12: v1(9066,7998) 9074,7998 9101,8025 9264,8025 9307,7982 v1(9367,7982)
GSM_RX: "Bypass d.2" Z4.6 | length 287.8
  Top Layer w15: Z4.6 9495,8856 9497,8854
GSM_TX: "Bypass d.1" Z4.5 | length 287.8
  Top Layer w15: Z4.5 9595,8856 9597,8854
NC: U3.24
NetA6_1: A6.1 D13.2 T8.3 | length 460.7
  Top Layer w15: D13.2@9041,7242 9041,6941 A6.1
  Bottom Layer w30: T8.3 9040.99,6941.01 A6.1
NetA6_2: A6.2 D14.2 T9.3 | length 461.1
  Top Layer w15: D14.2@8841,7242 8841,6941 A6.2
  Bottom Layer w30: T9.3 8839.99,6942.01 A6.2
NetA6_3: A6.3 D15.2 T10.3 | length 465.7
  Top Layer w15: D15.2@8640,7242 8640,6942 A6.3
  Bottom Layer w15: A6.3@8639.99,6942.01 A6.3
  Bottom Layer w30: T10.3 8643,7091.99 A6.3
NetA7_1: A7.1 D10.2 T5.3 | length 461.2
  Top Layer w15: A7.1 9644,6940 D10.2@9644,7244
  Bottom Layer w30: A7.1 9644.99,6940.99 T5.3
NetA7_2: A7.2 D11.2 T6.3 | length 461.4
  Top Layer w15: A7.2 D11.2@9443,7244
  Bottom Layer w30: A7.2 9443.99,6939.99 T6.3
NetA7_3: A7.3 D12.2 T7.3 | length 465.7
  Top Layer w15: D12.2@9239,7244 9239,6943 A7.3
  Bottom Layer w30: T7.3 9237.99,6944.01 A7.3
NetA8_1: A8.1 D8.2 T3.3 | length 461.7
  Top Layer w15: D8.2@10041,7244 10041,6941 A8.1
  Bottom Layer w30: T3.3 10043,7091.99 A8.1
NetA8_2: A8.2 D9.2 T4.3 | length 462.1
  Top Layer w15: D9.2@9840,7244 9840,6942 A8.2
  Bottom Layer w30: T4.3 9840.99,6941.01 A8.2
NetA9_1: A9.1 D6.2 T1.3 | length 459.8
  Top Layer w15: D6.2 10443,6940 A9.1
  Bottom Layer w30: T1.3 10442.99,6940.01 A9.1
NetA9_2: A9.2 D7.2 T2.3 | length 457.2
  Top Layer w15: A9.2@10241,6942 D7.2@10241,7244
  Bottom Layer w30: T2.3 10240.99,6942.01 A9.2
NetC6_2: C6.2 U2.4 | length 86.6
  Top Layer w15: C6.2 10292.24,8232.76 U2.4
NetC11_1: C11.1 R10.2 Z2.1 | length 546.2
  Top Layer w15: R10.2 10594,9017 10797,9220 10803.84,9220 Z2.1
  Bottom Layer w15: Z2.1 10823.06,9324.06 C11.1
NetC12_1: C12.1 U3.17 | length 167.2
  Bottom Layer w12: U3.17 10761.84,9002.16 10774,8990 C12.1@10814,8990
NetC18_1: C18.1 U4.62 | length 157
  Top Layer w15: U4.62 8561,8675.41 8561,8605 v1(8570,8605)
  Bottom Layer w15: v1(8570,8605) 8568,8603 8568,8596 8582,8582 C18.1@8626,8582
NetC19_1: C19.1 U4.24 X1.1 | length 266.5
  Top Layer w15: U4.24 8721.25,7999.75 X1.1
  Bottom Layer w15: C19.1 X1.1
NetC20_1: C20.1 U4.23 X1.2 | length 264.4
  Top Layer w15: X1.2 8689.76,7993.67 U4.23
  Bottom Layer w15: C20.1@8611,7844 8611,7914.91 X1.2
NetC21_2: C21.2 L1.1 U4.64 | length 290.2
  Top Layer w12: L1.1 8392,8761 8474.82,8678.18 U4.64 8500.78,8755.22 C21.2@8488,8768
NetD1_2: D1.2 R3.2 | length 240.5
  Top Layer w12: v1(11224,9392) 11225,9393 D1.2
  Bottom Layer w12: R3.2 11202,9370 v1(11224,9392)
NetD2_2: D2.2 R4.2 | length 379.7
  Top Layer w12: v1(11153,9392) 11153,9400 11187,9434 11187,9565 11193,9571 D2.2@11225,9571
  Bottom Layer w12: R4.2 11102,9341 v1(11153,9392)
NetD3_1: D3.1 U4.19 | length 4774.3
  Top Layer w10: v1(7937,7034) 7937,7026 7846,6935 7843,6935 7843,6867 7886,6824 10498,6824 10627,6953 10714,6953 10755,6994 D3.1 ; v1(8101,7620) 8103,7620 8172,7689 8214.28,7689 8280.28,7755 8409,7755 v1(8455,7801) ; v1@8511.32,7883.69 8507,7888 8507,7978.89 8563.77,8035.66 U4.19
  Top Layer w15: v1(8511.32,7879.17) v1@8511.32,7883.69
  Bottom Layer w12: v1(7937,7034) 8101,7198 v1(8101,7620)
  Bottom Layer w15: v1(8455,7801) 8511.32,7857.31 v1(8511.32,7879.17)
NetD3_2: D3.2 R7.2 | length 194.3
  Top Layer w15: D3.2 10997,7154 R7.2
NetD4_1: D4.1 U4.18 | length 5542.8
  Top Layer w10: v1(7863,7033) 7802,6972 7802,6842 7845,6799 10787,6799 10796,6808 10796,7327 10789,7334 D4.1 ; v1(8014,7620) 7944,7690 7944,7874 8009,7939 8192,7939 8293,7838 8392,7838 v1(8404,7850) ; v1(8463,7932) 8472,7941 8472,7975 8532.28,8035.28 U4.18
  Bottom Layer w12: v1@7861,7031 v1(7863,7033)
  Bottom Layer w15: v1(7863,7033) 8014,7184 v1(8014,7620) ; v1(8404,7850) 8404,7858 8457,7911 8457,7926 v1(8463,7932)
NetD4_2: D4.2 R8.2 | length 187.2
  Top Layer w15: D4.2 11014,7334 R8.2
NetD5_1: D5.1 U4.43 | length 3099.3
  Top Layer w12: U4.43@9039.44,8457 U4.43 9174.74,8455.74 9222,8503 9285,8503 9327,8461 v1(9327,7945) ; v1(9791,7735) 9836.71,7689.29 9836.71,7686.29 ; 9830,7693 9836.71,7686.29 ; v1(10623,7240) 10750,7240 D5.1 ; v1(10829,7440) 10811.5,7457.5 10546.5,7457.5 10529,7440 10083,7440 9836.71,7686.29
  Bottom Layer w12: v1(9327,7945) 9413,7859 9418.71,7859 9419.39,7859.69 9514.31,7859.69 9639,7735 v1(9791,7735) ; v1(10623,7240) 10619,7240 10619,7267 10646,7294 10805,7294 10829,7318 v1(10829,7440)
NetD5_2: D5.2 R9.2 | length 202.5
  Top Layer w15: D5.2@10840,7236 D5.2 11008,7245 R9.2
NetD6_1: D6.1 R36.2 | length 144.1
  Top Layer w12: D6.1 10543.5,7219.5 R36.2
NetD7_1: D7.1 R37.2 | length 142.4
  Top Layer w12: D7.1 10341,7219 R37.2
NetD8_1: D8.1 R38.2 | length 138.6
  Top Layer w12: D8.1 R38.2
NetD9_1: D9.1 R39.2 | length 140.2
  Top Layer w12: D9.1 9937,7222 R39.2
NetD10_1: D10.1 R40.2 | length 134.4
  Top Layer w12: D10.1 R40.2
NetD11_1: D11.1 R41.2 | length 137.4
  Top Layer w12: D11.1 9539,7224 R41.2
NetD12_1: D12.1 R42.2 | length 141.4
  Top Layer w12: D12.1 9334,7224 R42.2
NetD13_1: D13.1 R43.2 | length 134.4
  Top Layer w12: D13.1 R43.2@9136,7224
NetD14_1: D14.1 R44.2 | length 139.2
  Top Layer w12: D14.1 8844,7319 R44.2
NetD15_1: D15.1 R45.2 | length 139.8
  Top Layer w15: D15.1 8644,7320 R45.2
NetD16_1: D16.1 R46.2 | length 137.4
  Top Layer w12: D16.1 8541,7224 R46.2
NetD16_2: "Wyjscia cyfrowe.1" D16.2 T11.3 | length 462.9
  Top Layer w15: 8443,6939 8446,6942 D16.2@8446,7241
  Bottom Layer w30: 8443,6939 8446.99,6942.99 T11.3
NetD17_1: D17.1 R47.2 | length 142.2
  Top Layer w12: D17.1 8245,7319 R47.2
NetD17_2: "Wyjscia cyfrowe.2" D17.2 T12.3 | length 460.5
  Top Layer w15: D17.2@8240,7241 8240,6942 8243,6939
  Bottom Layer w25: 8239.99,6942.01 8243,6939
  Bottom Layer w30: 8239.99,6942.01 T12.3
NetR1_2: R1.2 R2.1 U1.1 | length 243.3
  Bottom Layer w25: R1.2 R2.1 10400.32,7933.69 U1.1
NetR3_1: R3.1 U3.23 | length 796.7
  Bottom Layer w15: U3.23 10810.39,8848.61 10837,8822 11085,8822 11202,8939 R3.1
NetR4_1: R4.1 U3.22 | length 710.6
  Bottom Layer w15: U3.22 10841.8,8874.2 10862,8854 11058,8854 11109,8905 11109,9119 R4.1
NetR10_1: R10.1 R11.2 U3.19 | length 407.2
  Top Layer w15: R11.2 R10.1 10459,8945 10482,8968 10538,8968 v1(10539,8969)
  Bottom Layer w12: v1(10539,8969) 10545,8969 10563.02,8950.98 U3.19
NetR12_1: R12.1 R24.2 T1.2 | length 280.1
  Bottom Layer w12: T1.2 10405,7192 10449,7236 R12.1 10449,7288 10550,7389 R24.2
NetR13_1: R13.1 R25.2 T2.2 | length 279.6
  Bottom Layer w12: T2.2 10203,7193 10245,7235 10245,7278 10347,7380 R25.2
NetR14_1: R14.1 R26.2 T3.2 | length 279.1
  Bottom Layer w12: T3.2 10003,7200 10047,7244 10047,7285 10148,7386 R26.2
NetR15_1: R15.1 R27.2 T4.2 | length 278.6
  Bottom Layer w12: T4.2 9803,7222 R15.1 9947,7366 R27.2
NetR16_1: R16.1 R28.2 T5.2 | length 275.7
  Bottom Layer w12: T5.2 9607,7239 9744,7376 R28.2
NetR17_1: R17.1 R29.2 T6.2 | length 275.2
  Bottom Layer w12: T6.2 9406,7225 R17.1 9544,7363 R29.2
NetR18_1: R18.1 R30.2 T7.2 | length 276.6
  Bottom Layer w12: T7.2 9200,7218 R18.1 9344,7362 R30.2
NetR19_1: R19.1 R31.2 T8.2 | length 276.4
  Bottom Layer w12: T8.2 9003,7239 9144,7380 R31.2
NetR20_1: R20.1 R32.2 T9.2 | length 276.4
  Bottom Layer w12: T9.2 8802,7243 8943,7384 R32.2
NetR21_1: R21.1 R33.2 T10.2 | length 276.4
  Bottom Layer w12: T10.2 8602,7231 8743,7372 R33.2
NetR22_1: R22.1 R34.2 T11.2 | length 271.1
  Bottom Layer w12: T11.2 8409,7247 8542,7380 R34.2
NetR23_1: R23.1 R35.2 T12.2 | length 273.2
  Bottom Layer w12: T12.2 8202,7225 R23.1 8340,7363 R35.2
NetU3_15: U3.15 Z2.3 | length 302.6
  Top Layer w15: v1(10745,9075) 10864,9075 10901.8,9112.8 Z2.3
  Bottom Layer w15: U3.15 10723.34,9053.34 v1(10745,9075)
NetU3_16: U3.16 Z2.2 | length 264.8
  Bottom Layer w15: U3.16 10789.75,9027.75 10822,9060 10822,9139.73 Z2.2
OTH1: U4.39 Z8.1 | length 1662.6
  Top Layer w15: v1@8891,8303 8960,8303 8986.76,8329.76 U4.39
  Bottom Layer w15: Z8.1 7635,8532 7687,8584 7930,8584 8042,8472 8857,8472 8895,8434 8895,8309.1 v1(8896.05,8308.05) ; v1@8891,8303 v1(8896.05,8308.05) ; v1@8899,8311 v1(8896.05,8308.05)
OTH2: U4.40 Z8.3 | length 1925.4
  Top Layer w15: v1(8946,8355) 8946,8361 8946.25,8361.25 U4.40
  Bottom Layer w15: Z8.3@7640,8409 Z8.3 7587,8409 7554,8442 7554,8553 7634,8633 7960,8633 8084,8509 8922,8509 8945,8486 8945,8356 v1(8946,8355)
OTH3: U4.6 Z8.5 | length 861.6
  Top Layer w15: Z8.5 7685,8359 8015,8359 8111.74,8455.74 U4.6
OTH4: U4.8 Z8.7 | length 876.9
  Top Layer w15: Z8.7 7685.02,8259.02 8085.02,8259.02 8218.75,8392.75 U4.8
OTH5: U4.41 Z8.9 | length 1520.7
  Top Layer w15: v1(8816,8359) 8866,8359 8899.75,8392.75 U4.41
  Bottom Layer w15: Z8.9 7685,8159 7843,8159 8043,8359 8277,8359 v1(8816,8359)
OTH6: U4.4 Z8.2 | length 704.9
  Top Layer w15: Z8.2 7744.73,8518.73 U4.4
OTH7: U4.5 Z8.4 | length 733.2
  Top Layer w15: Z8.4 7994,8409 8072.24,8487.24 U4.5
OTH8: U4.7 Z8.6 | length 748.6
  Top Layer w15: Z8.6 8055,8309 8170.24,8424.24 U4.7
OTH9: U4.42 Z8.8 | length 1397.7
  Top Layer w15: v1(8849,8421) 8849,8425 8849.76,8424.24 U4.42
  Bottom Layer w15: Z8.8 7796,8209 8008,8421 v1@8848,8421 ; v1@8848,8421 8849,8422 v1(8849,8421) v1@8848,8421
OTH10: U4.9 Z8.10 | length 805.3
  Top Layer w15: Z8.10 7924,8109 7982,8167 8077,8167 8271.25,8361.25 U4.9
PK1: R23.2 Z3.7 | length 1085.5
  Bottom Layer w15: R23.2@8242,7396 8242,7476 8365,7599 9157,7599 Z3.7
PK2: R22.2 Z3.14 | length 872.9
  Bottom Layer w15: R22.2@8443,7396 8445,7398 8445,7468 8547,7570 9142,7570 Z3.14
PK3: R21.2 Z3.6 | length 839.2
  Top Layer w15: v3(8672,7505) 8860,7693 9219,7693 Z3.6
  Bottom Layer w15: R21.2@8643,7396 8643,7476 v3(8672,7505)
PK4: R20.2 Z3.13 | length 573.5
  Bottom Layer w15: R20.2@8843,7396 8843,7436 8938,7531 9106,7531 9171,7466 9224,7466 Z3.13
PK5: R19.2 Z3.5 | length 512.2
  Top Layer w10: v3(9044,7478) 9044,7525 9094,7575 9333,7575 Z3.5
  Bottom Layer w15: R19.2@9044,7396 v3(9044,7478)
PK6: R18.2 Z3.12 | length 222.4
  Bottom Layer w15: R18.2@9245,7396 9245,7428 9277,7460 9334,7460 9385,7511 Z3.12
PK7: R17.2 Z3.4 | length 255.9
  Bottom Layer w15: R17.2@9445,7396 9445,7454 9435,7464 9435,7577 Z3.4
PK8: R16.2 Z3.11 | length 256.4
  Bottom Layer w15: Z3.11 9488,7524 9488,7494 9520,7462 9621,7462 9645,7438 R16.2@9645,7396
PK9: R15.2 Z3.3 | length 426.2
  Bottom Layer w15: Z3.3 9633,7579 9633,7499 9669,7463 9817,7463 9847,7433 R15.2@9847,7396
PK10: R14.2 Z3.10 | length 556.1
  Top Layer w12: Z3.10 9651,7461 9836,7461 v1(9869,7494)
  Bottom Layer w15: v1(9869,7494) 9907,7456 10007,7456 10049,7414 R14.2@10049,7396
PK11: R13.2 Z3.2 | length 679.8
  Top Layer w15: Z3.2 9738,7574 9765.49,7574 ; 9765.52,7574.03 9883.97,7574.03 v3(9956,7502)
  Bottom Layer w15: v3(9956,7502) 10178,7502 10248,7432 R13.2@10248,7396
PK12: R12.2 Z3.9 | length 881.2
  Bottom Layer w15: Z3.9 9732.03,7574.03 10064.97,7574.03 ; 10065,7574 10191,7574 10307,7458 10428,7458 10449,7437 R12.2@10449,7396
PWM1: U4.15 Z9.3 | length 1207.5
  Top Layer w12: v1(8156,8096) 8222,8162 8360,8162 8370.28,8172.28 U4.15
  Bottom Layer w12: Z9.3 7742,7560 7874,7692 7874,7984 7986,8096 v1(8156,8096)
PWM2: U4.16 Z9.2 | length 1352.8
  Top Layer w12: Z9.2 7967,7360 v1(8175,7568) ; v1(8241,8055) 8260,8074 8312,8074 8378.78,8140.78 U4.16
  Bottom Layer w12: v1(8175,7568) 8241,7634 v1(8241,8055)
PWR: U4.31 Z4.8 | length 1638
  Top Layer w12: U4.31 8941.72,8031.28 8954,8019 9019,8019 v1(9051,8051)
  Top Layer w15: Z4.8 9268,9114 9268,8566 9374,8460 9374,8059 v1(9363,8048)
  Bottom Layer w12: v1(9051,8051) 9360,8051 v1(9363,8048)
RI: U4.17 Z4.2 | length 3699.5
  Top Layer w12: v1@8412,7672 8573,7672 8636,7735 v1(9014,7735) ; v1(8428,8000) 8500.78,8072.78 U4.17 ; v1(9487,7773) 9707,7773 9836,7902 9836,9097 9608,9325 9517,9325 9495,9303 Z4.2
  Bottom Layer w12: v1(8412,7671) 8357,7726 8357,7929 v1(8428,8000) ; v1@9025,7724 9382,7724 9436,7724 v1@9485,7773
RST: C17.2 R6.1 S2.2 U4.20 Z5.5 | length 4223.2
  Top Layer w10: v2(8548,7967) 8548,7982 8595.27,8029.27 U4.20 ; 9008,7900 9389,7900 9457,7968 9457,8173 ; v1(9410,8665) 9410.99,8664.01 9410.99,8537.01 9457,8491 9457,8173 ; Z5.5 9458,8174 9457,8173 ; v1(10079,9324) 10079,9356 10137,9414 10500,9414 S2.2@10659,9573
  Bottom Layer w10: v2(8548,7967) 8548,7807 8583,7772 8703,7772 8735,7804 8896,7804 8996,7904 v1@8996,7912 ; v1(9410,8665) 9411.53,8666.53 9411.53,8696.53 9446,8731 9446,8792 9458,8804 9757,8804 9791,8838 9791,9036 v1(10079,9324)
  Bottom Layer w15: S2.2@10659,9573 10785,9573 ; C17.2@10784,9637 10785,9636 10785,9573 ; S2.2@10909,9573 10785,9573
  other v1: 8991,7911
RXD0: "Bypass c.2" U4.2 Z5.1 | length 3157.8
  Top Layer w10: Z5.1 9545,8474 9478,8541 9478,8649 9424,8703 9363,8703 9336,8730 9336,8777 9362,8803 9655,8803 9697,8845 9697,8854
  Top Layer w15: v1(8221,8698) 8337.28,8581.72 U4.2
  Bottom Layer w15: v1(8221,8698) 8165,8698 8103,8760 8103,8825 8261,8983 9653,8983 9697,8939 9697,8854
RXD1: "Bypass b.2" U4.27 | length 2493
  Top Layer w12: U4.27 8815.74,7979.26 8958,7837 9287,7837 9410,7714 9696,7714 v1@9840,7858 ; 9397,8754 9406,8754 9464,8696 9658,8696 9716,8638 v1(9716,8136)
  Bottom Layer w10: v1@9855,7860 9855,7968
  Bottom Layer w12: v1(9716,8136) 9855,7997 9855,7968
  other v1: 9857,7858
S1: C16.2 R5.1 S1.2 U4.10 | length 5216.9
  Top Layer w10: v1(7896,6909) 7896,6896 7944,6848 10487,6848 10578,6939 10578,6961 S1.2@10661,7044
  Top Layer w15: v1(8032,8043) 8318.76,8329.76 U4.10
  Bottom Layer w12: v1(7896,6909) 7792,7013 7792,7041 7952,7201 7952,7682 7930,7704 7930,7941 v1(8032,8043)
  Bottom Layer w15: R5.1 10715,7098 10661,7044 10787,7044 ; C16.2@10790,6991 10790,7041 10787,7044 ; S1.2@10911,7044 10787,7044
SCK: U4.11 Z5.7 | length 1229.4
  Top Layer w10: U4.11 8509.26,8298.26 v1(8524,8313)
  Top Layer w12: U4.11@8435.08,8299 U4.11
  Bottom Layer w12: v1(8524,8313) 8525,8314 8531,8314 8599,8246 8965.7,8246 8981.7,8262 9357,8262 Z5.7
STATUS: U4.26 Z4.3 | length 2715.2
  Top Layer w12: U4.26 8785,8076.57 v1(8785,8136) ; v1(9277,8156) 9277,8326 v1(9278,8327) ; Z4.3 9395,9282 9469,9356 9665,9356 9880,9141 9880,8977 ; v1(9878,8485) 9878,8975 9880,8977 ; 9880,8962 9880,8977
  Bottom Layer w12: v1(8785,8136) 9257,8136 v1(9277,8156) ; v1(9278,8327) 9411,8460 9853,8460 v1(9878,8485)
TXD0: "Bypass b.1" U4.3 Z5.9 | length 2995.8
  Top Layer w10: v1@9530.16,8621.84 9585,8567 9585,8489 9595,8479 9595,8024 Z5.9
  Top Layer w15: v1(8173,8794) 8173,8654 8276.77,8550.23 U4.3 ; 9383,8854 9397,8854
  Bottom Layer w10: 9249,8924 9249,8717 9302,8664 9302,8663 9340,8663 9389,8614 9522.32,8614 v1(9529.5,8621.18)
  Bottom Layer w15: v1(8173,8794) 8303,8924 9249,8924 9327,8924 9397,8854
TXD1: "Bypass c.1" U4.28 | length 1898.7
  Top Layer w12: U4.28 8847.24,7995.76 8971,7872 9673,7872 9757,7956 9757,8694 9697,8754
USB_UART_RX: "Bypass a.2" U3.5 | length 923
  Top Layer w15: v1(10161,8834) 10283,8834 v1(10284,8835)
  Bottom Layer w15: 9597,8754 9597,8690 9609,8678 9738,8678 9895,8835 10160,8835 v1(10161,8834) ; v1(10284,8835) 10303.43,8835 10315.41,8823.02 U3.5
USB_UART_TX: "Bypass a.1" U3.1 | length 1009.2
  Top Layer w15: v1(10163,8731) 10283,8731 v1@10284,8732
  Bottom Layer w12: 9501,8750 9497,8754 9497,8705 9564,8638 9751,8638 9844,8731 v1(10163,8731) ; v1@10284,8732 10299,8732 10310.34,8720.66 U3.1
  other v1: 10285,8720
VCC: C3.1 C4.1 C5.1 C13.1 C14.1 D1.1 D2.1 GSM_ZAS.3 GSM_ZAS.4 R2.2 U1.2 U2.1 U2.3 U3.20 | length 4338.5
  Top Layer w15: C5.1 10212,8027 C3.1 ; U2.3 10352.7,8326.14 10352.7,8299.79 10366.5,8286 10411.5,8286 10425.3,8299.79 10425.3,8326.14 U2.1 ; C13.1 10726,8928 v1(10747,8949) ; 10839,8692 10938,8791 11065,8791 11156,8882 11156,9202 11105,9253 11105,9383.08 11107.79,9385.88 11107.79,9424.79 11149,9466 D1.1 11149,9571 D2.1
  Top Layer w20: v1(10747,8949) 10839,8857 10839,8692 10788,8641 10788,8499 C14.1 10778,8492 C14.1@10771,8492
  Top Layer w25: U2.1@10430.5,8327.24 10430.5,8369.4 10464.1,8403 v1(10614,8403) 10682,8403 C14.1@10771,8492
  Top Layer w30: U1.2 10520,7837.43 10520,8082 v2@10614,8176
  Top Layer w80: C3.1 10212,7733 C4.1 10283,7662 10454,7662 ; GSM_ZAS.4 GSM_ZAS.3 10454,7662 ; U1.2 10500.32,7708.31 10454,7662
  Bottom Layer w15: 10454,7493 GSM_ZAS.3 ; U3.20 10718.39,8925.39 10742,8949 v1(10747,8949)
  Bottom Layer w25: U1.2 10516,7833.43 R2.2
  Bottom Layer w30: v2(10614,8180) v1(10614,8403)
pads on no net: U3.2 U3.3 U3.6 U3.8 U3.9 U3.10 U3.11 U3.12 U3.13 U3.14 U3.27 U3.28 U4.1 U4.12 U4.13 U4.25 U4.29 U4.32 Z2.6 Z3.1 Z3.8 Z4.4 Z5.3
copper on no net: | length 21.7
  Top Layer w10: 8433.37,8264.31 8435.82,8266.76 ; 8435.82,8235.27 8436.55,8236
  Top Layer w12: 8435.55,8235 8435.82,8235.27
  Top Layer w15: 10806.21,9239.21 10823.06,9239.21

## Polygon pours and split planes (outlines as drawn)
GND on Bottom Layer "Bottom Layer-No Net" (solid): 7471,6765 11273,6765 11273,9870 7471,9870
GND on Top Layer "Bottom Layer-No Net" (solid): 7471,6765 11273,6765 11273,9870 7471,9870

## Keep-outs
Keep-Out Layer:
  lines w5: 7471,9778 7471,9870 10766,9870 ; 7471,9801 7471,9487 7471,9435 7471,6765 10580,6765 ; 9829,6765 11273,6765 11273,9870 10750,9870 ; 11169,7370 11170,7369

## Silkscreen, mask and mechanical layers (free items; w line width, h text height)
Top Overlay:
  lines w5: 8220,7387 8240,7366 ; 8241,7480 8240,7480 8240,7366 ; 8261,7388 8240,7366 ; 10351,8329 10352,8329
  text "R. Krawczyk" at 7999,9110 h60 r270
  text "Sterownik GSM" at 8080,9107 h60 r270
  text "Bypass" at 9373,8947 h60
  text "D7-D18" at 8205,7506 h60
  text "R36-R47" at 8295,7422 h60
